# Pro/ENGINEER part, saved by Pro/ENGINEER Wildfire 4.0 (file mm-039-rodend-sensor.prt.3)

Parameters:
  METRIC = "NO"

Other parameters: PITCH, DRILL_POINT_ANGLE, DRILL_DEPTH, DRILL_DIAMETER, THREAD_DIAMETER, THREADS_PER_INCH, THREAD_DEPTH, THREAD_LENGTH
